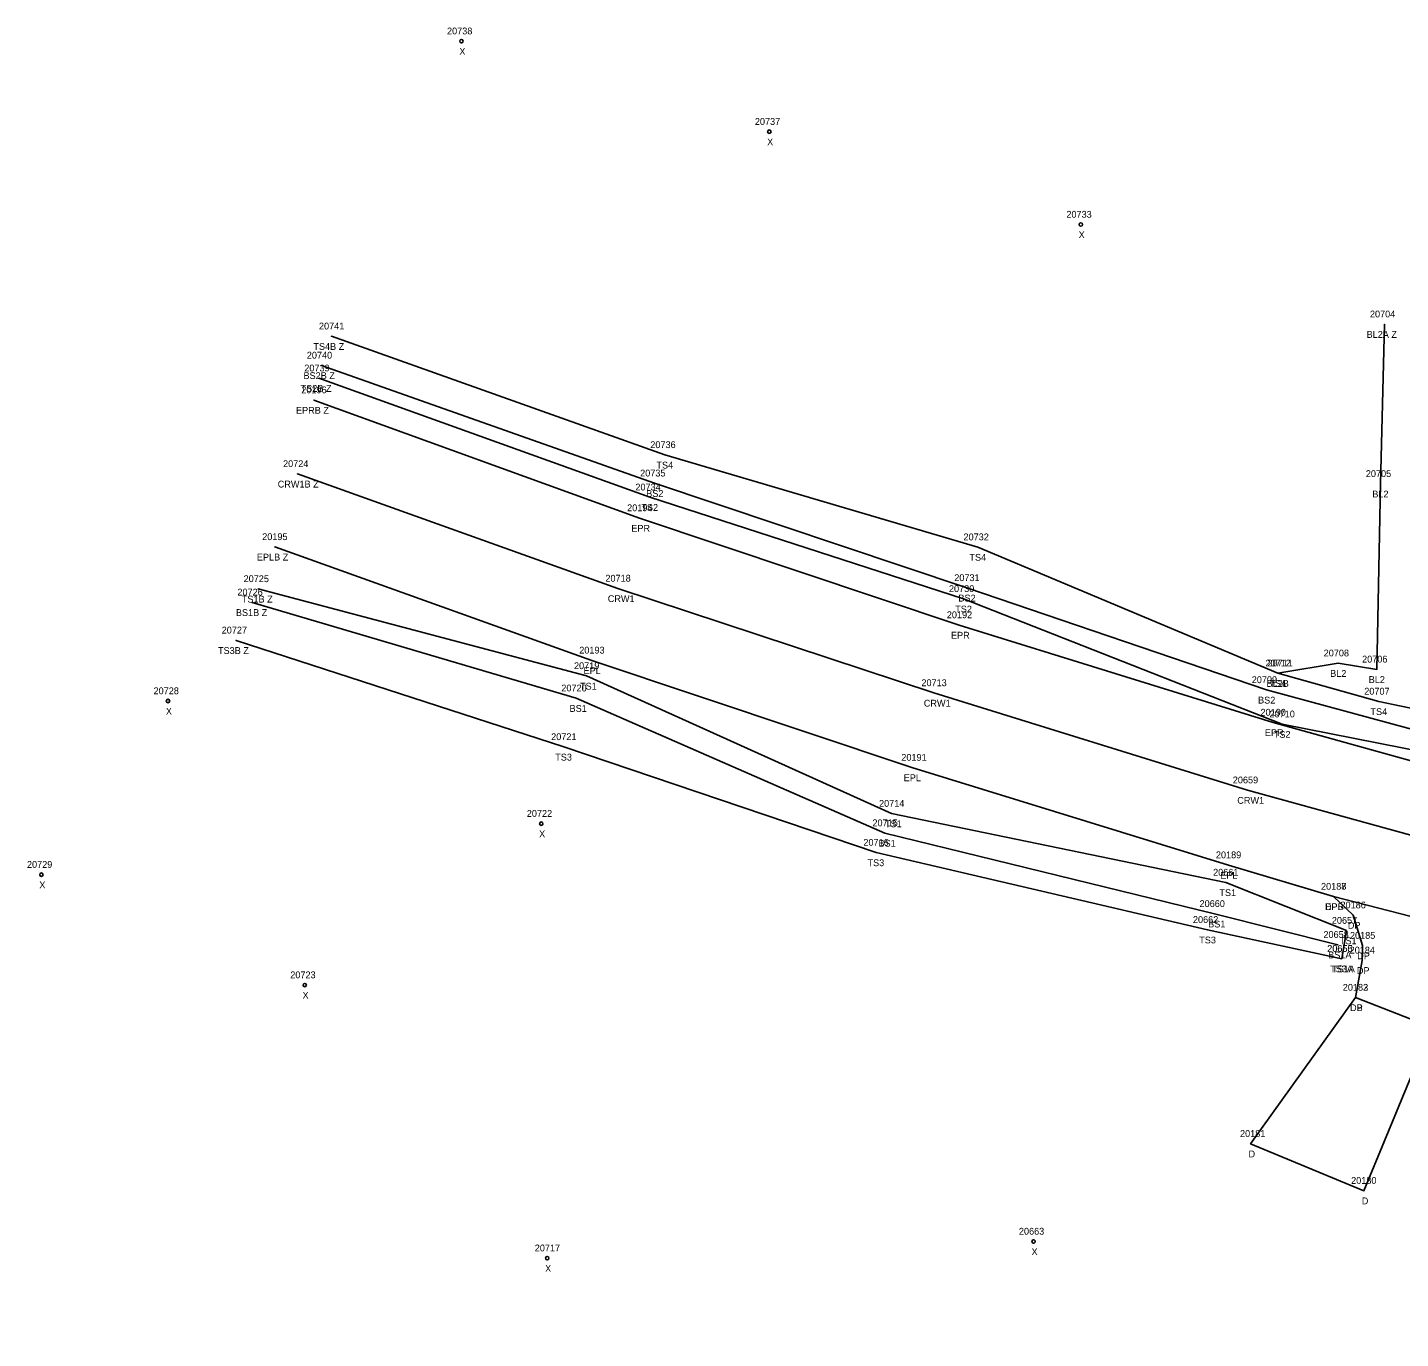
# Model space of a CAD drawing. Extents: x 1813127 to 1818290, y 1178171 to 1179900.
# Drawn here: x 1813127 to 1813328.5, y 1178739.3 to 1178931.8 of the extents above; entities that cross this region are included whole.
import ezdxf

# ---------------------------------------------------------------- set-up
doc = ezdxf.new("R2010")
doc.units = 0
for name, color, linetype in [('RD_DTM_BkLn1', 7, 'Continuous'), ('RD_DTM_BkLn2', 7, 'Continuous'), ('RD_EX_Driveway', 7, 'Continuous'), ('RD_EX_Driveway_txCode', 7, 'Continuous'), ('RD_EX_Road', 7, 'Continuous'), ('RD_EX_Road_txCode', 7, 'Continuous'), ('RD_SMD_Locator', 7, 'Continuous'), ('RD_SMD_Misc', 7, 'Continuous')]:
    doc.layers.add(name, color=color, linetype=linetype)

msp = doc.modelspace()

# ---------------------------------------------------------------- linework, layer by layer
at = {"layer": 'RD_DTM_BkLn1'}
for points in [[(1813326.2, 1178888.27), (1813325.6, 1178864.83), (1813325.07, 1178837.59), (1813319.4, 1178838.49), (1813310.54, 1178837.02)], [(1813740.76, 1178717.86), (1813693.97, 1178742.65), (1813652.18, 1178753.85), (1813643.74, 1178755.64), (1813595, 1178763.51), (1813546.44, 1178770.61), (1813497.6, 1178777.62), (1813448.59, 1178785.89), (1813401.09, 1178795.04), (1813353.48, 1178806.76), (1813306.05, 1178819.85), (1813260.03, 1178834.12), (1813213.64, 1178849.47), (1813166.61, 1178866.29)]]:
    msp.add_lwpolyline(points, dxfattribs=at)
at = {"layer": 'RD_DTM_BkLn2'}
for points in [[(1813399.11, 1178862.51), (1813400.66, 1178834.59), (1813396.83, 1178814.37), (1813357.41, 1178822.74), (1813331.9, 1178831.52), (1813325.37, 1178832.88), (1813310.54, 1178837.02), (1813266.49, 1178855.54), (1813220.54, 1178869.08), (1813171.6, 1178886.5)], [(1813400.27, 1178862.81), (1813401.78, 1178834.6), (1813398.4, 1178812.49), (1813398.37, 1178811.29), (1813357.2, 1178821.49), (1813308.85, 1178834.57), (1813264.85, 1178849.55), (1813219.03, 1178864.91), (1813170.13, 1178882.22)], [(1813401.59, 1178862.81), (1813403.02, 1178834.61), (1813400.13, 1178813.23), (1813399.37, 1178809.66), (1813357.07, 1178820.51), (1813311.17, 1178829.54), (1813264.4, 1178847.94), (1813218.33, 1178862.86), (1813169.73, 1178880.34)], [(1813319.93, 1178795.1), (1813320.59, 1178799.23), (1813302.9, 1178806.3), (1813253.81, 1178816.41), (1813209.04, 1178836.62), (1813160.82, 1178849.4)], [(1813319.35, 1178797.15), (1813301.23, 1178801.69), (1813252.84, 1178813.55), (1813207.5, 1178833.35), (1813159.94, 1178847.43)], [(1813319.93, 1178795.1), (1813300.22, 1178799.35), (1813251.54, 1178810.69), (1813205.69, 1178826.2), (1813157.6, 1178841.85)]]:
    msp.add_lwpolyline(points, dxfattribs=at)
at = {"layer": 'RD_EX_Driveway'}
for points in [[(1813343.23, 1178797.92), (1813338.76, 1178793.46), (1813333.1, 1178785.04), (1813321.9, 1178789.4), (1813322.9, 1178794.86), (1813322.95, 1178797.03), (1813321.57, 1178801.49), (1813318.7, 1178804.23)], [(1813333.1, 1178785.04), (1813323.15, 1178761.04), (1813306.52, 1178767.93), (1813321.9, 1178789.4)]]:
    msp.add_lwpolyline(points, dxfattribs=at)
at = {"layer": 'RD_EX_Road'}
for points in [[(1813522.62, 1178785.74), (1813518.21, 1178785.19), (1813499.47, 1178787.87), (1813450.56, 1178796.06), (1813414.35, 1178802.92), (1813398.64, 1178806.42), (1813355.44, 1178817.13), (1813309.85, 1178829.79), (1813263.76, 1178844.1), (1813216.84, 1178859.81), (1813169.03, 1178877.13)], [(1813732.94, 1178707.95), (1813689.88, 1178731.75), (1813641.71, 1178744.36), (1813593.37, 1178752.09), (1813544.49, 1178758.77), (1813495.45, 1178766.29), (1813446.8, 1178774.66), (1813426.54, 1178777.95), (1813403.21, 1178782.55), (1813398.65, 1178783.84), (1813350.68, 1178796.09), (1813343.23, 1178797.92), (1813318.7, 1178804.23), (1813303.26, 1178808.85), (1813256.8, 1178823.17), (1813209.81, 1178838.91), (1813163.27, 1178855.57)]]:
    msp.add_lwpolyline(points, dxfattribs=at)
at = {"layer": 'RD_SMD_Locator'}
for centre, radius in [((1813190.68, 1178929.83), 0.25), ((1813235.87, 1178916.54), 0.25), ((1813281.6, 1178902.91), 0.25), ((1813326.2, 1178888.27), 0.001), ((1813171.6, 1178886.5), 0.001), ((1813170.13, 1178882.22), 0.001), ((1813169.73, 1178880.34), 0.001), ((1813169.03, 1178877.13), 0.001), ((1813220.54, 1178869.08), 0.001), ((1813166.61, 1178866.29), 0.001), ((1813219.03, 1178864.91), 0.001), ((1813325.6, 1178864.83), 0.001), ((1813218.33, 1178862.86), 0.001), ((1813216.84, 1178859.81), 0.001), ((1813163.27, 1178855.57), 0.001), ((1813266.49, 1178855.54), 0.001), ((1813160.82, 1178849.4), 0.001), ((1813213.64, 1178849.47), 0.001), ((1813264.85, 1178849.55), 0.001), ((1813159.94, 1178847.43), 0.001), ((1813264.4, 1178847.94), 0.001), ((1813263.76, 1178844.1), 0.001), ((1813157.6, 1178841.85), 0.001), ((1813209.81, 1178838.91), 0.001), ((1813319.4, 1178838.49), 0.001), ((1813209.04, 1178836.62), 0.001), ((1813310.54, 1178837.02), 0.001), ((1813310.54, 1178837.02), 0.001), ((1813325.07, 1178837.59), 0.001), ((1813308.85, 1178834.57), 0.001), ((1813147.6, 1178832.94), 0.25), ((1813207.5, 1178833.35), 0.001), ((1813260.03, 1178834.12), 0.001), ((1813325.37, 1178832.88), 0.001), ((1813309.85, 1178829.79), 0.001), ((1813311.17, 1178829.54), 0.001), ((1813205.69, 1178826.2), 0.001), ((1813256.8, 1178823.17), 0.001), ((1813306.05, 1178819.85), 0.001), ((1813253.81, 1178816.41), 0.001), ((1813202.39, 1178814.93), 0.25), ((1813252.84, 1178813.55), 0.001), ((1813251.54, 1178810.69), 0.001), ((1813303.26, 1178808.85), 0.001), ((1813129.02, 1178807.44), 0.25), ((1813302.9, 1178806.3), 0.001), ((1813318.7, 1178804.23), 0.001), ((1813318.7, 1178804.23), 0.001), ((1813301.23, 1178801.69), 0.001), ((1813321.57, 1178801.49), 0.001), ((1813300.22, 1178799.35), 0.001), ((1813320.59, 1178799.23), 0.001), ((1813319.35, 1178797.15), 0.001), ((1813322.95, 1178797.03), 0.001), ((1813319.93, 1178795.1), 0.001), ((1813319.93, 1178795.1), 0.001), ((1813322.9, 1178794.86), 0.001), ((1813167.67, 1178791.23), 0.25), ((1813321.9, 1178789.4), 0.001), ((1813321.9, 1178789.4), 0.001), ((1813306.52, 1178767.93), 0.001), ((1813323.15, 1178761.04), 0.001), ((1813274.67, 1178753.58), 0.25), ((1813203.27, 1178751.13), 0.25)]:
    msp.add_circle(centre, radius, dxfattribs=at)

# ---------------------------------------------------------------- texts
at = {"layer": 'RD_EX_Driveway_txCode'}
for s, p in [('20187', (1813316.86, 1178805.23)), ('DPB', (1813317.44, 1178802.23)), ('20186', (1813319.71, 1178802.49)), ('DP', (1813320.79, 1178799.49)), ('20185', (1813321.11, 1178798.03)), ('20184', (1813321.06, 1178795.86)), ('DP', (1813322.17, 1178795.03)), ('DP', (1813322.12, 1178792.86)), ('20182', (1813320.06, 1178790.4)), ('20183', (1813320.06, 1178790.4)), ('DB', (1813321.12, 1178787.4)), ('DP', (1813321.12, 1178787.4)), ('20181', (1813304.97, 1178768.93)), ('D', (1813306.22, 1178765.93)), ('20180', (1813321.28, 1178762.04)), ('D', (1813322.84, 1178759.04))]:
    msp.add_text(s, height=1, dxfattribs=at).set_placement(p)
at = {"layer": 'RD_EX_Road_txCode'}
for s, p in [('20196', (1813167.17, 1178878.13)), ('EPRB Z', (1813166.39, 1178875.13)), ('20194', (1813215, 1178860.81)), ('EPR', (1813215.61, 1178857.81)), ('20195', (1813161.43, 1178856.57)), ('EPLB Z', (1813160.65, 1178853.57)), ('20192', (1813261.93, 1178845.1)), ('EPR', (1813262.54, 1178842.1)), ('20193', (1813207.97, 1178839.91)), ('EPL', (1813208.6, 1178836.91)), ('20190', (1813307.98, 1178830.79)), ('EPR', (1813308.62, 1178827.79)), ('20191', (1813255.25, 1178824.17)), ('EPL', (1813255.6, 1178821.17)), ('20189', (1813301.43, 1178809.85)), ('EPL', (1813302.06, 1178806.85)), ('20188', (1813316.86, 1178805.23)), ('EPL', (1813317.49, 1178802.23))]:
    msp.add_text(s, height=1, dxfattribs=at).set_placement(p)
at = {"layer": 'RD_SMD_Misc'}
for s, p in [('20738', (1813188.56, 1178930.83)), ('X', (1813190.37, 1178927.83)), ('20737', (1813233.75, 1178917.54)), ('X', (1813235.55, 1178914.54)), ('20733', (1813279.48, 1178903.91)), ('X', (1813281.28, 1178900.91)), ('20704', (1813324.04, 1178889.27)), ('20741', (1813169.76, 1178887.5)), ('BL2A Z', (1813323.55, 1178886.27)), ('TS4B Z', (1813168.94, 1178884.5)), ('20740', (1813167.98, 1178883.22)), ('BS2B Z', (1813167.49, 1178880.22)), ('20739', (1813167.61, 1178881.34)), ('TS2B Z', (1813167.07, 1178878.34)), ('20736', (1813218.4, 1178870.08)), ('20724', (1813164.49, 1178867.29)), ('20735', (1813216.91, 1178865.91)), ('TS4', (1813219.3, 1178867.08)), ('20705', (1813323.44, 1178865.83)), ('CRW1B Z', (1813163.71, 1178864.29)), ('20734', (1813216.21, 1178863.86)), ('BS2', (1813217.8, 1178862.91)), ('BL2', (1813324.39, 1178862.83)), ('TS2', (1813217.09, 1178860.86)), ('20732', (1813264.38, 1178856.54)), ('TS4', (1813265.25, 1178853.54)), ('20725', (1813158.7, 1178850.4)), ('20718', (1813211.81, 1178850.47)), ('20731', (1813263.02, 1178850.55)), ('20726', (1813157.79, 1178848.43)), ('CRW1', (1813212.16, 1178847.47)), ('20730', (1813262.24, 1178848.94)), ('BS2', (1813263.63, 1178847.55)), ('BS1B Z', (1813157.57, 1178845.43)), ('TS1B Z', (1813158.44, 1178847.4)), ('TS2', (1813263.16, 1178845.94)), ('20727', (1813155.48, 1178842.85)), ('TS3B Z', (1813154.94, 1178839.85)), ('20708', (1813317.25, 1178839.49)), ('20719', (1813207.2, 1178837.62)), ('20712', (1813308.71, 1178838.02)), ('20711', (1813308.99, 1178838.02)), ('20706', (1813322.89, 1178838.59)), ('20709', (1813306.69, 1178835.57)), ('BL2', (1813318.2, 1178836.49)), ('BL2', (1813323.86, 1178835.59)), ('20728', (1813145.48, 1178833.94)), ('20720', (1813205.34, 1178834.35)), ('TS1', (1813208.08, 1178834.62)), ('20713', (1813258.2, 1178835.12)), ('BL2B', (1813308.86, 1178835.02)), ('TS4', (1813309.3, 1178835.02)), ('20707', (1813323.21, 1178833.88)), ('BS1', (1813206.55, 1178831.35)), ('CRW1', (1813258.55, 1178832.12)), ('BS2', (1813307.62, 1178832.57)), ('X', (1813147.29, 1178830.94)), ('20710', (1813309.3, 1178830.54)), ('TS4', (1813324.12, 1178830.88)), ('TS2', (1813309.93, 1178827.54)), ('20721', (1813203.85, 1178827.2)), ('TS3', (1813204.44, 1178824.2)), ('20659', (1813303.91, 1178820.85)), ('20714', (1813251.98, 1178817.41)), ('CRW1', (1813304.57, 1178817.85)), ('20722', (1813200.27, 1178815.93)), ('20715', (1813251.01, 1178814.55)), ('TS1', (1813252.85, 1178814.41)), ('X', (1813202.08, 1178812.93)), ('20716', (1813249.68, 1178811.69)), ('BS1', (1813251.9, 1178811.55)), ('20729', (1813126.9, 1178808.44)), ('TS3', (1813250.29, 1178808.69)), ('20661', (1813301.02, 1178807.3)), ('X', (1813128.71, 1178805.44)), ('TS1', (1813301.94, 1178804.3)), ('20660', (1813299.03, 1178802.69)), ('20662', (1813298.06, 1178800.35)), ('BS1', (1813300.29, 1178799.69)), ('20657', (1813318.45, 1178800.23)), ('TS3', (1813298.98, 1178797.35)), ('20658', (1813317.21, 1178798.15)), ('TS1', (1813319.63, 1178797.23)), ('20656', (1813317.76, 1178796.1)), ('20655', (1813317.79, 1178796.1)), ('BS1A', (1813317.91, 1178795.15)), ('TS3A', (1813318.2, 1178793.1)), ('TS1A', (1813318.48, 1178793.1)), ('20723', (1813165.55, 1178792.23)), ('X', (1813167.35, 1178789.23)), ('20663', (1813272.51, 1178754.58)), ('20717', (1813201.44, 1178752.13)), ('X', (1813274.36, 1178751.58)), ('X', (1813202.96, 1178749.13))]:
    msp.add_text(s, height=1, dxfattribs=at).set_placement(p)

doc.saveas('drawing.dxf')
